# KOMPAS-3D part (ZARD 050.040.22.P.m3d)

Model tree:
1. Плоскость XY
2. Плоскость ZX
3. Плоскость ZY
4. Ось X
5. Ось Y
6. Ось Z
7. Начало координат
8. Булева операция:1
9. Булева операция:2
10. Булева операция:3
11. Булева операция:4
